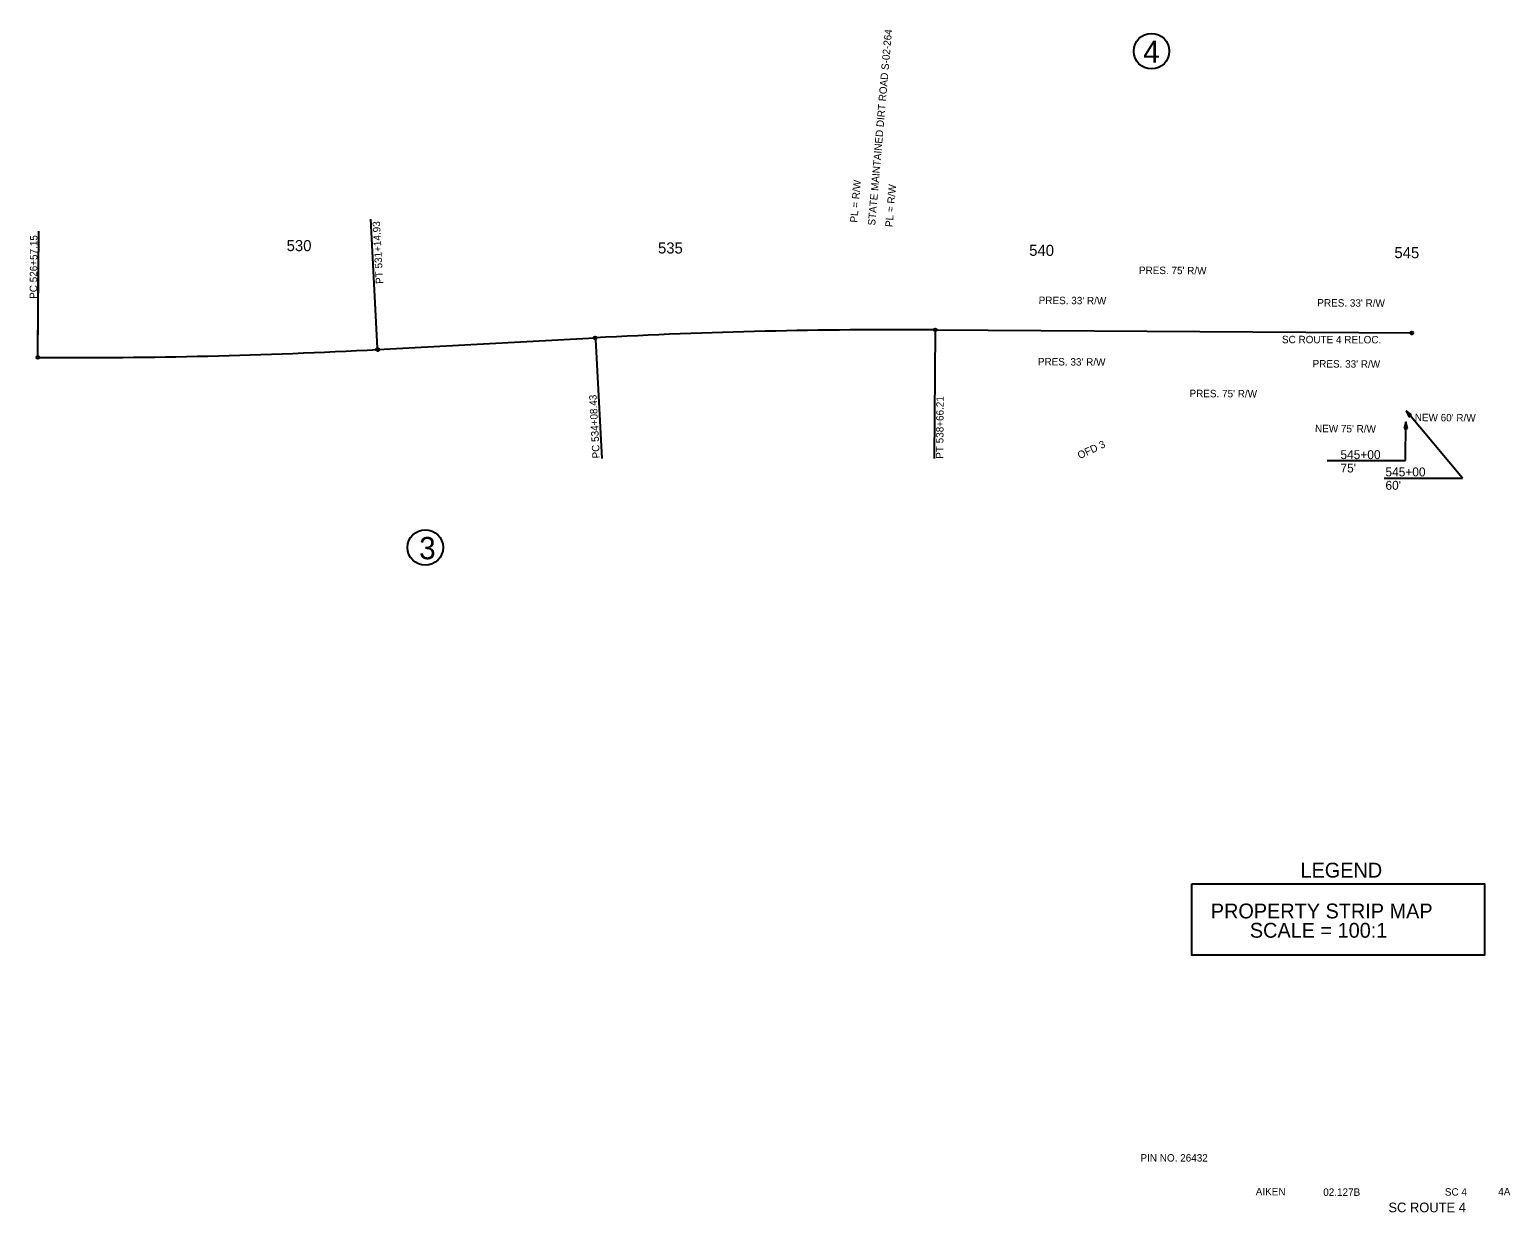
# Model space of a CAD drawing. Extents: x -64038 to -60892, y 1838 to 8465.
# Drawn here: x -62886 to -60892, y 3788 to 5381 of the extents above; entities that cross this region are included whole.
import ezdxf

# ---------------------------------------------------------------- set-up
doc = ezdxf.new("R2010")
doc.units = 0
for name, color, linetype in [('Level 1', 7, 'Continuous'), ('Level 13', 7, 'Continuous'), ('Level 19', 7, 'Continuous'), ('Level 21', 7, 'Continuous'), ('Level 24', 7, 'Continuous'), ('Level 25', 7, 'Continuous'), ('Level 33', 7, 'Continuous')]:
    doc.layers.add(name, color=color, linetype=linetype)

msp = doc.modelspace()

# ---------------------------------------------------------------- linework, layer by layer
at = {"layer": 'Level 1'}
msp.add_lwpolyline([(-61321.2, 4230.5), (-60927.4, 4230.5), (-60927.4, 4134.3), (-61321.2, 4134.3)], close=True, dxfattribs=at)
at = {"layer": 'Level 19'}
for p, q in [((-62417.8, 4952.1), (-62427.1, 5125.7)), ((-62875.3, 4941.4), (-62874.2, 5109.7)), ((-62875.3, 4941), (-62874.4, 5082.3)), ((-62417.7, 4950.1), (-62124.7, 4965.8)), ((-61667.1, 4974.6), (-61668.2, 4803.4)), ((-61667.1, 4976.6), (-61025.1, 4972.5)), ((-62124.6, 4963.8), (-62116, 4803.5))]:
    msp.add_line(p, q, dxfattribs=at)
for centre in [(-62124.7, 4965.8), (-61667.1, 4976.6), (-61025.1, 4972.5), (-62417.7, 4950.1), (-62875.3, 4939.4)]:
    msp.add_circle(centre, 2, dxfattribs=at)
for centre, start, end in [((-61716, -2662.8), 89.63338, 93.06665), ((-62826.4, 12578.8), 269.63337, 273.06663)]:
    msp.add_arc(centre, 7639.6, start, end, dxfattribs=at)
at = {"layer": 'Level 24'}
for p, q in [((-61032.9, 4867.6), (-61028.8, 4859.2)), ((-61025.4, 4862.1), (-61032.9, 4867.6)), ((-61033, 4852.6), (-61035.4, 4843.6)), ((-61030.9, 4843.5), (-61033, 4852.6)), ((-61028.8, 4859.2), (-61025.4, 4862.1)), ((-61035.4, 4843.6), (-61030.9, 4843.5))]:
    msp.add_line(p, q, dxfattribs=at)
at = {"layer": 'Level 25'}
for centre in [(-61375.7, 5352), (-62353.6, 4683.4)]:
    msp.add_circle(centre, 23.9, dxfattribs=at)
at = {"layer": 'Level 33'}
for p, q in [((-60956.8, 4777), (-61032.9, 4867.6)), ((-61033.6, 4800.4), (-61033, 4852.6)), ((-61139, 4800.4), (-61033.6, 4800.4)), ((-61062.2, 4777), (-60956.8, 4777))]:
    msp.add_line(p, q, dxfattribs=at)

# ---------------------------------------------------------------- texts
at = {"layer": 'Level 1'}
msp.add_text('OFD 3', height=10, rotation=24.993, dxfattribs=at).set_placement((-61472.4, 4802.4))
for s, height, p in [('LEGEND', 20, (-61175, 4238.8)), ('PROPERTY STRIP MAP', 20, (-61295.8, 4183.8)), ('SCALE = 100:1', 20, (-61243.2, 4157.8)), ('PIN NO. 26432', 10, (-61390.5, 3856.3)), ('AIKEN', 10, (-61235.3, 3810.8)), ('02.127B', 10, (-61144.4, 3810.1)), ('SC 4', 10, (-60980.6, 3810.4)), ('4A', 10, (-60908.7, 3810.8))]:
    msp.add_text(s, height=height, dxfattribs=at).set_placement(p)
at = {"layer": 'Level 13'}
for s, rotation, p in [("PRES. 75' R/W", 359.6333, (-61392.6, 5051.9)), ("PRES. 33' R/W", 359.6333, (-61527.6, 5011.4)), ("PRES. 33' R/W", 359.6333, (-61152.4, 5008.1)), ('SC ROUTE 4 RELOC.', 359.8979, (-61200, 4958.6)), ("PRES. 33' R/W", 359.6333, (-61528.7, 4928.8)), ("PRES. 33' R/W", 359.6333, (-61158.8, 4926)), ("PRES. 75' R/W", 359.6333, (-61324.5, 4886))]:
    msp.add_text(s, height=10, rotation=rotation, dxfattribs=at).set_placement(p)
msp.add_text('SC ROUTE 4', height=13, dxfattribs=at).set_placement((-61056.6, 3788))
at = {"layer": 'Level 19'}
for s, rotation, p in [('PT 531+14.93', 93.0666, (-62410.2, 5038.8)), ('PC 526+57.15', 89.6334, (-62876.4, 5018.3)), ('PC 534+08.43', 93.0667, (-62118.5, 4803.7)), ('PT 538+66.21', 89.6334, (-61656, 4802.9))]:
    msp.add_text(s, height=10, rotation=rotation, dxfattribs=at).set_placement(p)
at = {"layer": 'Level 21'}
for s, p in [('530', (-62540.4, 5082.7)), ('535', (-62040.3, 5079.5)), ('540', (-61540.4, 5076.3)), ('545', (-61048.6, 5073.2))]:
    msp.add_text(s, height=15, rotation=359.6333, dxfattribs=at).set_placement(p)
at = {"layer": 'Level 25'}
for s, rotation, p in [('STATE MAINTAINED DIRT ROAD S-02-264', 85.0581, (-61747.8, 5116.8)), ('PL = R/W', 85.0661, (-61771.8, 5120.7)), ('PL = R/W', 85.0661, (-61724.4, 5114.7))]:
    msp.add_text(s, height=10, rotation=rotation, dxfattribs=at).set_placement(p)
for s, p in [('4', (-61386.9, 5336.3)), ('3', (-62361.9, 4667.6))]:
    msp.add_text(s, height=30, dxfattribs=at).set_placement(p)
at = {"layer": 'Level 33'}
for s, p in [("NEW 75' R/W", (-61155.5, 4838.8)), ("NEW 60' R/W", (-61021.2, 4853.7))]:
    msp.add_text(s, height=10, rotation=359.5312, dxfattribs=at).set_placement(p)
for s, p in [('545+00', (-61121.2, 4802.5)), ("75'", (-61121.2, 4784.5)), ('545+00', (-61060.6, 4779.2)), ("60'", (-61060.6, 4761.2))]:
    msp.add_text(s, height=12, dxfattribs=at).set_placement(p)

doc.saveas('drawing.dxf')
